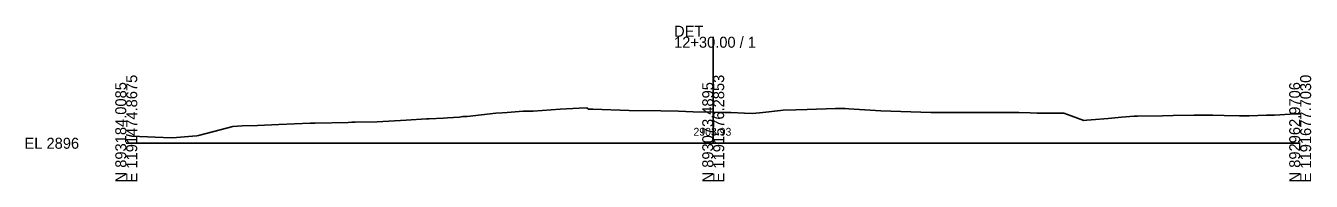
# Model space of a CAD drawing. Extents: x -26 to 1303, y -10 to 9537.
# Drawn here: x 974.3 to 1302.8, y 1490.3 to 1530 of the extents above; entities that cross this region are included whole.
import ezdxf

# ---------------------------------------------------------------- set-up
doc = ezdxf.new("R2010")
doc.units = 0
for name, color, linetype in [('Default', 7, 'Continuous'), ('Exist Cross Section Cell', 7, 'Continuous'), ('Exist XS Center Line Elevation Label', 7, 'Continuous'), ('Exist XS Ground Line', 7, 'Continuous')]:
    doc.layers.add(name, color=color, linetype=linetype)

msp = doc.modelspace()

# ---------------------------------------------------------------- linework, layer by layer
at = {"layer": 'Exist Cross Section Cell'}
for p, q in [((1150, 1500), (1150, 1527.18)), ((1000, 1500), (1150, 1500)), ((1150, 1500), (1300, 1500))]:
    msp.add_line(p, q, dxfattribs=at)
at = {"layer": 'Exist XS Ground Line'}
for p, q in [((1097.36, 1507.88), (1101.47, 1508.16)), ((1101.47, 1508.16), (1104.01, 1508.17)), ((1104.01, 1508.17), (1110.93, 1508.66)), ((1110.93, 1508.66), (1115.74, 1508.94)), ((1115.74, 1508.94), (1117.69, 1509.06)), ((1117.69, 1509.06), (1118.1, 1508.69)), ((1118.1, 1508.69), (1119.25, 1508.68)), ((1119.25, 1508.68), (1128.48, 1508.36)), ((1128.48, 1508.36), (1136.59, 1508.25)), ((1136.59, 1508.25), (1141.13, 1508.16)), ((1141.13, 1508.16), (1144.85, 1508.06)), ((1144.85, 1508.06), (1150, 1507.93)), ((1162.7, 1507.88), (1167.23, 1508.39)), ((1167.23, 1508.39), (1167.89, 1508.42)), ((1167.89, 1508.42), (1171.08, 1508.56)), ((1171.08, 1508.56), (1174.04, 1508.61)), ((1174.04, 1508.61), (1181.26, 1508.9)), ((1181.26, 1508.9), (1183.69, 1508.85)), ((1183.69, 1508.85), (1184.66, 1508.77)), ((1184.66, 1508.77), (1192.84, 1508.25)), ((1192.84, 1508.25), (1205.61, 1507.85)), ((1033.53, 1504.51), (1038.96, 1504.75)), ((1038.96, 1504.75), (1047.02, 1505.09)), ((1047.02, 1505.09), (1048.29, 1505.15)), ((1048.29, 1505.15), (1056.73, 1505.34)), ((1056.73, 1505.34), (1057.63, 1505.36)), ((1057.63, 1505.36), (1058.5, 1505.36)), ((1058.5, 1505.36), (1064.1, 1505.44)), ((1064.1, 1505.44), (1071.54, 1505.9)), ((1071.54, 1505.9), (1076.77, 1506.2)), ((1076.77, 1506.2), (1077.41, 1506.22)), ((1077.41, 1506.22), (1081.08, 1506.42)), ((1081.08, 1506.42), (1082.09, 1506.46)), ((1082.09, 1506.46), (1085.19, 1506.64)), ((1085.19, 1506.64), (1085.98, 1506.83)), ((1085.98, 1506.83), (1087.1, 1506.87)), ((1087.1, 1506.87), (1094.49, 1507.68)), ((1094.49, 1507.68), (1096.1, 1507.79)), ((1096.1, 1507.79), (1097.36, 1507.88)), ((1150, 1507.93), (1152.86, 1507.86)), ((1152.86, 1507.86), (1154.09, 1507.83)), ((1154.09, 1507.83), (1154.54, 1507.82)), ((1154.54, 1507.82), (1157.98, 1507.7)), ((1157.98, 1507.7), (1160.04, 1507.58)), ((1160.04, 1507.58), (1162.7, 1507.88)), ((1205.61, 1507.85), (1210.75, 1507.82)), ((1210.75, 1507.82), (1212.41, 1507.81)), ((1212.41, 1507.81), (1228.08, 1507.84)), ((1228.08, 1507.84), (1231.02, 1507.74)), ((1231.02, 1507.74), (1232.79, 1507.68)), ((1232.79, 1507.68), (1234.21, 1507.7)), ((1234.21, 1507.7), (1239.6, 1507.64)), ((1239.6, 1507.64), (1241.45, 1506.99)), ((1241.45, 1506.99), (1244.68, 1505.8)), ((1244.68, 1505.8), (1245.47, 1505.87)), ((1245.47, 1505.87), (1246.55, 1505.96)), ((1246.55, 1505.96), (1250.96, 1506.35)), ((1250.96, 1506.35), (1254.34, 1506.67)), ((1254.34, 1506.67), (1257.57, 1506.88)), ((1257.57, 1506.88), (1258.47, 1506.94)), ((1258.47, 1506.94), (1264.82, 1507.02)), ((1264.82, 1507.02), (1267.55, 1507.07)), ((1267.55, 1507.07), (1272.83, 1507.2)), ((1272.83, 1507.2), (1277.66, 1507.13)), ((1277.66, 1507.13), (1280.56, 1507.06)), ((1280.56, 1507.06), (1284.48, 1506.96)), ((1284.48, 1506.96), (1286.94, 1506.99)), ((1286.94, 1506.99), (1291.41, 1507.16)), ((1291.41, 1507.16), (1292.14, 1507.15)), ((1292.14, 1507.15), (1293.43, 1507.16)), ((1293.43, 1507.16), (1297.45, 1507.45)), ((1297.45, 1507.45), (1298.23, 1507.49)), ((1298.23, 1507.49), (1300, 1507.49)), ((1000, 1502.19), (1000.74, 1501.98)), ((1000.74, 1501.98), (1001.43, 1501.82)), ((1001.43, 1501.82), (1007.36, 1501.55)), ((1007.36, 1501.55), (1011.54, 1501.36)), ((1011.54, 1501.36), (1012.84, 1501.49)), ((1012.84, 1501.49), (1016.95, 1501.82)), ((1016.95, 1501.82), (1018.03, 1501.92)), ((1018.03, 1501.92), (1018.49, 1501.95)), ((1018.49, 1501.95), (1024.01, 1503.43)), ((1024.01, 1503.43), (1027.2, 1504.3)), ((1027.2, 1504.3), (1029.66, 1504.41)), ((1029.66, 1504.41), (1033.53, 1504.51))]:
    msp.add_line(p, q, dxfattribs=at)

# ---------------------------------------------------------------- texts
at = {"layer": 'Default'}
msp.add_text('-', height=0.0001, dxfattribs=at).set_placement((1000, 1500))
at = {"layer": 'Exist Cross Section Cell'}
for s, p in [('DET', (1140, 1527.18)), ('12+30.00 / 1', (1140, 1524.38)), ('EL 2896', (974, 1498.6))]:
    msp.add_text(s, height=2.8, dxfattribs=at).set_placement(p)
for s, p in [('N 893184.0085', (1000, 1490)), ('E 1191474.8675', (1002.8, 1490)), ('N 893073.4895', (1150, 1490)), ('E 1191576.2853', (1152.8, 1490)), ('N 892962.9706', (1300, 1490)), ('E 1191677.7030', (1302.8, 1490))]:
    msp.add_text(s, height=2.8, rotation=90, dxfattribs=at).set_placement(p)
at = {"layer": 'Exist XS Center Line Elevation Label'}
msp.add_text('2903.93', height=2, dxfattribs=at).set_placement((1144.96, 1501.93))

doc.saveas('drawing.dxf')
